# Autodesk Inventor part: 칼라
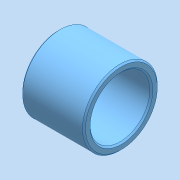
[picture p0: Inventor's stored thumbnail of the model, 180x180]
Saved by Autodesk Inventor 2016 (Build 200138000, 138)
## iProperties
Created: 2024-08
Part Number: 칼라
Material: 일반
Document SubType Name: Modeling
Designer: pc-7
Density: 1 g/cm^3
Appearance: 기본값
Author: jhkim
Sending System: Autodesk Inventor 2025
Preprocessor: ST-DEVELOPER v20
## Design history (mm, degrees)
node "칼라1"
node "솔리드2"
node "솔리드1"
